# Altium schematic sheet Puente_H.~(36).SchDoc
size A4
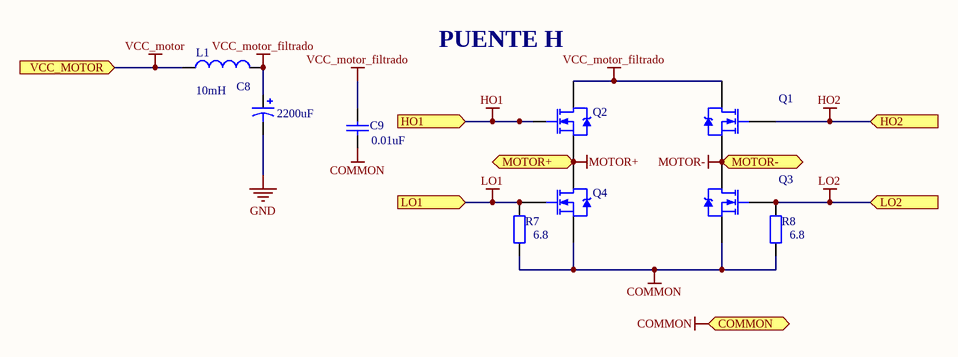
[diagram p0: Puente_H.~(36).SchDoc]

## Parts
C8  value 2200uF  [CAPPR5-13X16]  (hidden comment: Cap Pol1)
C9  value 0.01uF  [RAD-0.2]  (hidden comment: Cap)
L1  value 10mH  [bobina_Choque]  (hidden comment: Inductor)
Q1  IRF3205  [TO-220AB]  (value not drawn)
Q2  IRF3205  [TO-220AB]  (value not drawn)
Q3  IRF3205  [TO-220AB]  (value not drawn)
Q4  IRF3205  [TO-220AB]  (value not drawn)
R7  value 6.8  [AXIAL-0.3]  (hidden comment: Res2)
R8  value 6.8  [AXIAL-0.3]  (hidden comment: Res2)

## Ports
COMMON (out), HO1 (in), HO2 (in), LO1 (in), LO2 (in), MOTOR+ (bidir), MOTOR- (bidir), VCC_MOTOR (in)

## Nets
COMMON: C9.1 Q3.3(S) Q4.3(S) R7.1 R8.1 ; port COMMON
GND: C8.2
HO1: Q2.1(G) ; port HO1
HO2: Q1.1(G) ; port HO2
LO1: Q4.1(G) R7.2 ; port LO1
LO2: Q3.1(G) R8.2 ; port LO2
MOTOR+: Q2.3(S) Q4.2(D) ; port MOTOR+
MOTOR-: Q1.3(S) Q3.2(D) ; port MOTOR-
VCC_motor: L1.1 ; port VCC_MOTOR
VCC_motor_filtrado: C8.1 C9.2 L1.2 Q1.2(D) Q2.2(D)

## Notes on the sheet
- PUENTE H

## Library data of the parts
C8 = Cap Pol1: Polarized Capacitor (Radial)
C9 = Cap: Capacitor
L1 = Inductor: Code_IEC: 1005
Q1-Q4 = IRF3205: HEXFET Power MOSFET; Note: Pin 2 is electrically connected to pin 4.
R7 R8 = Res2: Resistor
